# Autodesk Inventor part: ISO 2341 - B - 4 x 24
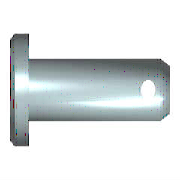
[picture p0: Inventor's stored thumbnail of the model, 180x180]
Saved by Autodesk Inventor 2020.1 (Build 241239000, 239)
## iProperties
Created: 2019-01
Part Number: ISO 2341 - B - 4 x 24
Material: Steel, Alloy
Description: Clevis pin
Document SubType Name: Modeling
Standard: ISO 2341
Designer: Safarabadi
Standards Organization: DIN
Language: en-US
Size Designation: B - 4 x 24
Categories: <MemberInstance><Categories><Category DisplayName="Fasteners" InternalName="e4da775c-781d-43d5-af7c-5136215cf5a6" Mnemonic="FSTN"><Category DisplayName="Pins" I
Density: 7.73 g/cm^3
Appearance: Semi-Polished
IsCustomPart: 1
Author: Safarabadi
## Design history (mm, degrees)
sketch "Sketch1"
  geometry: L1 (-1, 0)-(-1, 3); L2 (-1, 3)-(0, 3); L3 (0, 3)-(0, 2); L4 (0, 2)-(24, 2); L5 (24, 2)-(24, 0); L6 (-1, 0)-(24, 0); L7 (-6, 0)-(29, 0) reference; L8 (0, -1.2)-(0, 3.7) reference; C1 r 0.5 at (21.5, 0)
  constraints: 12 end point, 3 parallel, 2 collinear, 2 perpendicular, 1 centre point, 1 point on line, 1 vertical
  dimensions: "d0" = 4 diameter of L4 L6 (= NND); "d1" = 6 diameter of L2 L6 (= KOD); "d2" = 1 distance of L1.end L2.end (= KOH); "d3" = 24 distance of L3.end L4.end (= NLG); "d5" = 2.5 distance from line of L5 C1.centre (= DIST); "d6" = 1 diameter of C1 (= BOR)
revolve "Body" stored, may be unused: angle "d4" = 90 deg
extrude "Hole" cut sketch "Sketch1" extent not by distance; stored distance "d7" = 4 (= NND); taper "d8" = 0 deg
body "Solid1"
chamfer "Chamfer1" distance "d9" = 0.5 (= PHH2); stored, may be unused: angle "d10" = 45 deg (= FAWI2), second distance "d16" = 0.5 (= PHH2)
chamfer "Chamfer2" distance "d11" = 1 (= PHH1); stored, may be unused: angle "d12" = 30 deg (= FAWI1), second distance "d17" = 1 (= PHH1)
workaxis "Work Axis1"
workplane "Work Plane1"
other parameters: "PHH1" = 1 [user parameter; used in 2 equation terms], "PHH2" = 0.5 [user parameter; used in 2 equation terms], "KOD" = 6 [user parameter; used in 1 equation term], "KOH" = 1 [user parameter; used in 1 equation term], "NND" = 4 [user parameter; used in 2 equation terms], "FAWI1" = 30 deg [user parameter; used in 1 equation term], "FAWI2" = 45 deg [user parameter; used in 1 equation term], "DIST" = 2.5 [user parameter; used in 1 equation term], "BOR" = 1 [user parameter; used in 1 equation term], "NLG" = 24 [user parameter; used in 1 equation term], "d13" = 0, "d14" = 0, "d27" = 0, "d28" = 0, "d29" = 0, "d30" = 0, "d31" = 0
